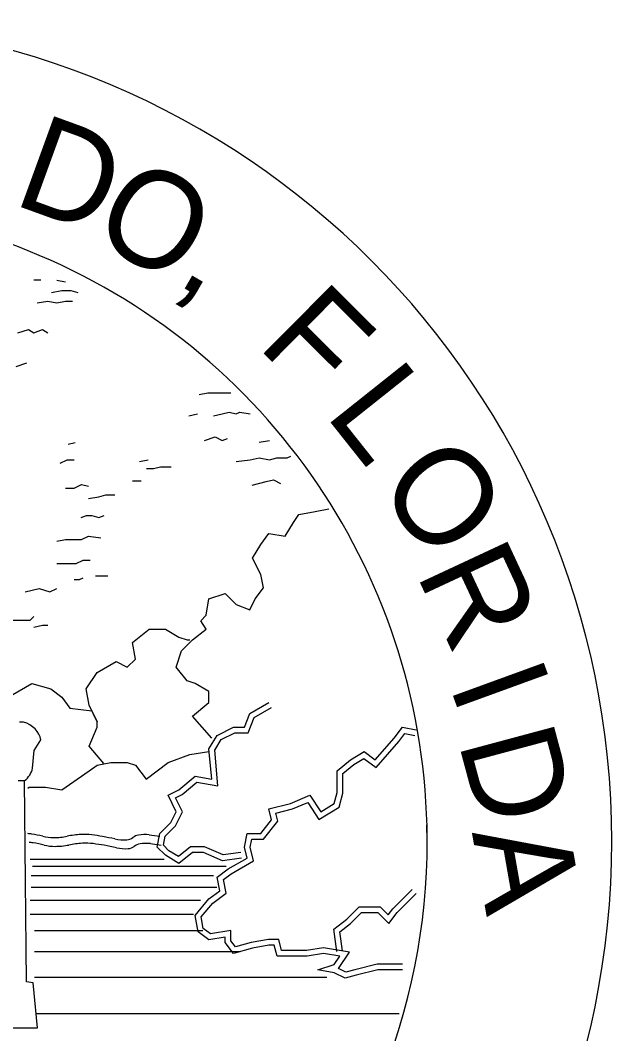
# Model space of a CAD drawing. Extents: x -7.1 to 10, y -5 to 6.
# Drawn here: x 6.3116 to 6.591, y -3.9297 to -3.4515 of the extents above; entities that cross this region are included whole.
import ezdxf

# ---------------------------------------------------------------- set-up
doc = ezdxf.new("R2010")
doc.units = 0
doc.layers.add('Level 60', color=7, linetype='Continuous')

msp = doc.modelspace()

# ---------------------------------------------------------------- linework, layer by layer
at = {"layer": 'Level 60'}
for p, q in [((6.321385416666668, -3.5740625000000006), (6.318031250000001, -3.5740625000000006)), ((6.328854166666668, -3.5740625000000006), (6.333010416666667, -3.574916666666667)), ((6.309708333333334, -3.614833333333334), (6.3146770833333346, -3.613135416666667)), ((6.391177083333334, -3.6380625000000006), (6.395343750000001, -3.6372395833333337)), ((6.334239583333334, -3.651583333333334), (6.337593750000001, -3.650739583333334)), ((6.4244062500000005, -3.6505208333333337), (6.429375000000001, -3.6497187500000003)), ((6.367895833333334, -3.6596666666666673), (6.372010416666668, -3.6588229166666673)), ((6.364593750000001, -3.6688125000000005), (6.368750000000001, -3.6688125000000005)), ((6.313083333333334, -3.782666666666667), (6.311218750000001, -3.782666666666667)), ((6.318218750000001, -3.7960937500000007), (6.321312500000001, -3.791083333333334)), ((6.318218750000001, -3.7960937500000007), (6.321312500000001, -3.791083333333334)), ((6.317416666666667, -3.8043645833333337), (6.318218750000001, -3.7960937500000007)), ((6.317416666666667, -3.8043645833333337), (6.318218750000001, -3.7960937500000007)), ((6.310656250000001, -3.8102500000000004), (6.313656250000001, -3.8102500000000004)), ((6.314645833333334, -3.905145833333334), (6.313656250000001, -3.8102500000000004)), ((6.372437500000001, -3.8358437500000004), (6.377593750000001, -3.836489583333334)), ((6.373145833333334, -3.8400104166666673), (6.37825, -3.8406666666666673)), ((6.316281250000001, -3.8473541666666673), (6.379666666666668, -3.8473541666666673)), ((6.317343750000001, -3.8506250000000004), (6.408906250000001, -3.8506250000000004)), ((6.316802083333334, -3.8550625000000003), (6.402854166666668, -3.8550625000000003)), ((6.316802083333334, -3.8605937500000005), (6.404489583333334, -3.8605937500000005)), ((6.316281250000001, -3.866645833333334), (6.396760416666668, -3.866645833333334)), ((6.316281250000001, -3.873239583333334), (6.393447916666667, -3.873239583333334)), ((6.318427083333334, -3.8810104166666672), (6.397895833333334, -3.8810104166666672)), ((6.318427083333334, -3.890916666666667), (6.415500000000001, -3.890916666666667)), ((6.317718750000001, -3.9056666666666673), (6.314645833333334, -3.905145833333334)), ((6.319708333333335, -3.9268437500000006), (6.317718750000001, -3.9056666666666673)), ((6.318427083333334, -3.9030625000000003), (6.456343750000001, -3.9030625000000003)), ((6.319020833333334, -3.920177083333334), (6.490520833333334, -3.920177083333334)), ((6.305104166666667, -3.9268437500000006), (6.319708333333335, -3.9268437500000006))]:
    msp.add_line(p, q, dxfattribs=at)
for points in [[(6.32634375, -3.579895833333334), (6.331333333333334, -3.579052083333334), (6.335447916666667, -3.579052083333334), (6.338822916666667, -3.579895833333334)], [(6.319687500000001, -3.5848854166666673), (6.3246979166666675, -3.5840625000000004), (6.328854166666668, -3.5848854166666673), (6.333010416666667, -3.5840625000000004), (6.336302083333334, -3.5840625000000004)], [(6.310531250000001, -3.599041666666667), (6.315520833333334, -3.5973437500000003), (6.318031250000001, -3.599041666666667), (6.322166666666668, -3.5973437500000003), (6.3246979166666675, -3.599041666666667)], [(6.396166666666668, -3.6281145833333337), (6.400281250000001, -3.6272916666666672), (6.404489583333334, -3.6272916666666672), (6.406968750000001, -3.6272916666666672), (6.411104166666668, -3.6272916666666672)], [(6.402854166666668, -3.6380625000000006), (6.406968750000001, -3.6372395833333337), (6.410302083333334, -3.636385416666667), (6.4136145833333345, -3.6372395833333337), (6.415260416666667, -3.636385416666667), (6.420270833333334, -3.6372395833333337)], [(6.398677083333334, -3.6497187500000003), (6.403656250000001, -3.6480416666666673), (6.406968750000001, -3.6497187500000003), (6.409447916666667, -3.648895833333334)], [(6.4136145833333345, -3.6596666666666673), (6.420270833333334, -3.6588229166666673), (6.4244062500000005, -3.658010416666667), (6.429375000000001, -3.6588229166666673), (6.432729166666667, -3.658010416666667), (6.437697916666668, -3.658010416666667), (6.439395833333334, -3.6572083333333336)], [(6.3304791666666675, -3.660520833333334), (6.3338125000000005, -3.6588229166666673), (6.337145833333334, -3.6588229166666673)], [(6.371229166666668, -3.663020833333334), (6.374520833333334, -3.663020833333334), (6.377875, -3.662197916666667), (6.382833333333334, -3.662197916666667)], [(6.333010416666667, -3.672197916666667), (6.337145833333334, -3.672197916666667), (6.340479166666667, -3.670489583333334), (6.343791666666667, -3.6713437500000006)], [(6.42121875, -3.6708750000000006), (6.427833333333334, -3.6691666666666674), (6.431166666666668, -3.6683645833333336), (6.434479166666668, -3.6700000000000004)], [(6.343791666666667, -3.6771562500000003), (6.348802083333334, -3.6763125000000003), (6.352083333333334, -3.6754791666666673), (6.356270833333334, -3.6754791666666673)], [(6.402031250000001, -3.7901875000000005), (6.393020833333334, -3.779854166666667), (6.400729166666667, -3.7734687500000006), (6.400729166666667, -3.7682708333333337), (6.394302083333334, -3.764447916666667), (6.390468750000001, -3.7631458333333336), (6.385291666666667, -3.7567395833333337), (6.387843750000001, -3.748989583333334), (6.393020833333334, -3.743833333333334), (6.399427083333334, -3.7387291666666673), (6.3968750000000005, -3.734833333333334), (6.399427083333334, -3.7322500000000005), (6.400729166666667, -3.7245520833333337), (6.408458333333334, -3.7220000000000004), (6.4136145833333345, -3.7271041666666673), (6.420041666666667, -3.7296562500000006), (6.422635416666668, -3.7245520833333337), (6.426489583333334, -3.7193750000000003), (6.425187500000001, -3.7129479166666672), (6.421364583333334, -3.705239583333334), (6.425187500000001, -3.6987812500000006), (6.429093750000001, -3.6936562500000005), (6.436770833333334, -3.6949375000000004), (6.440604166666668, -3.6885000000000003), (6.4431979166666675, -3.6846250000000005), (6.450927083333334, -3.683354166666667), (6.457385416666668, -3.6820729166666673)], [(6.340385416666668, -3.6860937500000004), (6.342895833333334, -3.685239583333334), (6.345395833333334, -3.685239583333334), (6.3487083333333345, -3.6860937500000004), (6.351239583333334, -3.685239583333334)], [(6.328854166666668, -3.6973229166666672), (6.333010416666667, -3.696520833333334), (6.337145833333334, -3.696520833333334), (6.340479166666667, -3.696520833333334), (6.343791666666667, -3.694885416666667), (6.3496250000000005, -3.6956875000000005)], [(6.328854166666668, -3.707864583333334), (6.3338125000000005, -3.707864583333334), (6.337979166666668, -3.707864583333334), (6.341312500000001, -3.706229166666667), (6.344645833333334, -3.706229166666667)], [(6.337145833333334, -3.715354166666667), (6.339635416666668, -3.715354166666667), (6.341312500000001, -3.714552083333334)], [(6.347125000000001, -3.7136979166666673), (6.350406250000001, -3.7136979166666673), (6.352916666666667, -3.7136979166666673)], [(6.313895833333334, -3.7211875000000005), (6.317197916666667, -3.7203645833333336), (6.320531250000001, -3.7195625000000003), (6.323010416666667, -3.7203645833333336), (6.325520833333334, -3.7211875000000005), (6.328854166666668, -3.7195625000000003)], [(6.303895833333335, -3.735354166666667), (6.307250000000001, -3.7345208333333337), (6.309708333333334, -3.7345208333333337), (6.313041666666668, -3.7345208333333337), (6.316354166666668, -3.7345208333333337), (6.318031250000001, -3.732822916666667)], [(6.318031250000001, -3.7378125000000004), (6.322166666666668, -3.736958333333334), (6.3246979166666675, -3.736958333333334)], [(6.351072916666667, -3.8021875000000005), (6.344125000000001, -3.794041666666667), (6.347979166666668, -3.785010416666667), (6.347979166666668, -3.782458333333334), (6.344125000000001, -3.7747291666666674), (6.342822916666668, -3.767020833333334), (6.347979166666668, -3.7593125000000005), (6.356979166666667, -3.754114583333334), (6.362135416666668, -3.7567395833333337), (6.365989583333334, -3.752885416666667), (6.3647083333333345, -3.7451354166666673), (6.372437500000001, -3.7387291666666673), (6.3801458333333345, -3.7387291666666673), (6.386572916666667, -3.7425625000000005), (6.390468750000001, -3.743833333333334), (6.391750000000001, -3.743833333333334)], [(6.263052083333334, -3.8197500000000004), (6.256604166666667, -3.815927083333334), (6.261750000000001, -3.8081979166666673), (6.268208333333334, -3.802989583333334), (6.273333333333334, -3.7953125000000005), (6.279760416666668, -3.7927604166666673), (6.288770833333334, -3.7862812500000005), (6.293947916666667, -3.7773020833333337), (6.299125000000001, -3.7734687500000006), (6.308052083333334, -3.769572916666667), (6.3170625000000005, -3.764447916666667), (6.326062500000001, -3.767020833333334), (6.331239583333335, -3.770895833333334), (6.33509375, -3.7760312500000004), (6.345395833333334, -3.7773020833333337), (6.347979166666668, -3.782458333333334)], [(6.416187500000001, -3.8468125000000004), (6.407177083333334, -3.8480937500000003), (6.3981770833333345, -3.844239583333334), (6.393020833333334, -3.844239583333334), (6.386572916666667, -3.8493645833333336), (6.3801458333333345, -3.8455104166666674), (6.376291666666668, -3.8416875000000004), (6.377593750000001, -3.835208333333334), (6.38271875, -3.830104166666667), (6.385291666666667, -3.8249270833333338), (6.3814375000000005, -3.8171770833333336), (6.386572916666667, -3.8146250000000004), (6.394302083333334, -3.8081979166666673), (6.402031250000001, -3.809520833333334), (6.400729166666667, -3.7953125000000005), (6.404625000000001, -3.7889270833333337), (6.4123333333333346, -3.785010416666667), (6.417458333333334, -3.785010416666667), (6.420041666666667, -3.778552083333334), (6.429093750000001, -3.7734687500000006)], [(6.415833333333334, -3.8441250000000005), (6.407531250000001, -3.845354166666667), (6.3987187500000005, -3.8415625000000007), (6.392072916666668, -3.8415625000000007), (6.386385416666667, -3.8461250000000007), (6.381791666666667, -3.843385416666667), (6.379239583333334, -3.8407604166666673), (6.380020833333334, -3.836489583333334), (6.384937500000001, -3.831666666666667), (6.388270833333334, -3.8249270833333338), (6.385010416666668, -3.8184062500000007), (6.388031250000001, -3.816864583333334), (6.395083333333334, -3.8110520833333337), (6.404979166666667, -3.8126875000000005), (6.403489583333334, -3.795927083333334), (6.406520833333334, -3.7909166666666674), (6.412947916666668, -3.787677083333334), (6.419302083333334, -3.787677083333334), (6.4221666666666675, -3.780447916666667), (6.4303645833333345, -3.7757187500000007)], [(6.492125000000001, -3.899572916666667), (6.480541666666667, -3.899572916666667), (6.470291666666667, -3.9021250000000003), (6.465083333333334, -3.9034479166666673), (6.4599375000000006, -3.9008958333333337), (6.452187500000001, -3.899572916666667), (6.4599375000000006, -3.897020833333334), (6.462510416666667, -3.893135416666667), (6.454781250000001, -3.891885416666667), (6.4471041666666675, -3.893135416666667), (6.440604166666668, -3.893135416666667), (6.432947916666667, -3.893135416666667), (6.431572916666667, -3.8879687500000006), (6.429093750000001, -3.8879687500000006), (6.421364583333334, -3.889260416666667), (6.4123333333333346, -3.891885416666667), (6.408458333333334, -3.886708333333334), (6.408458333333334, -3.884135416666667), (6.400729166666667, -3.8854062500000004), (6.395604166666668, -3.8815625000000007), (6.394302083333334, -3.8738750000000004), (6.400729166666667, -3.8661250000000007), (6.405906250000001, -3.862270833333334), (6.404625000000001, -3.855791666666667), (6.409760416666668, -3.8519687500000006), (6.4188125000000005, -3.8468125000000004), (6.417458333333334, -3.8416875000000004), (6.4188125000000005, -3.835208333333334), (6.425187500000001, -3.835208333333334), (6.4303437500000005, -3.8287812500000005), (6.429093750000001, -3.8236562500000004), (6.439322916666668, -3.8211250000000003), (6.448354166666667, -3.8171770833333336), (6.453510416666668, -3.8249270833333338), (6.4599375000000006, -3.8211250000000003), (6.461260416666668, -3.815927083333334), (6.461260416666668, -3.8055937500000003), (6.467666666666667, -3.800489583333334), (6.474114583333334, -3.7965937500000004), (6.47925, -3.800489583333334), (6.488250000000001, -3.7901875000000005), (6.492125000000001, -3.785010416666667), (6.498552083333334, -3.7862812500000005)], [(6.492125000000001, -3.8968958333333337), (6.480218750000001, -3.8968958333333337), (6.4696041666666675, -3.899572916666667), (6.465416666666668, -3.900604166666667), (6.461947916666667, -3.8988645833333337), (6.467072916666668, -3.891197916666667), (6.454781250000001, -3.889166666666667), (6.446843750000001, -3.890447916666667), (6.440604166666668, -3.890447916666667), (6.4350000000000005, -3.890447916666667), (6.4336979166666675, -3.8852916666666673), (6.428833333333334, -3.8852916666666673), (6.420750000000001, -3.886666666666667), (6.413354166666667, -3.888770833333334), (6.411156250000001, -3.885791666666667), (6.411156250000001, -3.8809479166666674), (6.401437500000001, -3.8825937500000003), (6.398062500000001, -3.880041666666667), (6.397135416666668, -3.874614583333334), (6.402593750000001, -3.8680833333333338), (6.408833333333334, -3.8634062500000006), (6.407562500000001, -3.8569062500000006), (6.411218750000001, -3.8541875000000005), (6.421854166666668, -3.8480937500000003), (6.420250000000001, -3.8415937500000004), (6.420958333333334, -3.8378541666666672), (6.426468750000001, -3.8378541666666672), (6.433229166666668, -3.8294166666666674), (6.432333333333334, -3.8255625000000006), (6.4402187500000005, -3.8236562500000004), (6.447385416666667, -3.820583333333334), (6.452697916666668, -3.8285729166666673), (6.462270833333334, -3.822822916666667), (6.463927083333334, -3.816229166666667), (6.463927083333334, -3.806916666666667), (6.469197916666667, -3.802708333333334), (6.473927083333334, -3.799854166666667), (6.479645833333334, -3.8041041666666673), (6.490375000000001, -3.7918437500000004), (6.493260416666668, -3.7879895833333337), (6.498010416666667, -3.788958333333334)], [(6.3151875, -3.8137916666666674), (6.315781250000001, -3.8133437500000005), (6.323531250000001, -3.8133437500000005), (6.331239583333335, -3.8146250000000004), (6.344125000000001, -3.8055937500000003), (6.347979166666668, -3.802989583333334), (6.354375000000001, -3.801760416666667), (6.362135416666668, -3.801760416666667), (6.365989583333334, -3.802989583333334), (6.371156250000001, -3.809520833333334), (6.3814375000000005, -3.801760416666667), (6.391750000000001, -3.7978854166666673), (6.400729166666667, -3.7965937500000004)], [(6.461135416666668, -3.8909375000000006), (6.459656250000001, -3.8803333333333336), (6.465916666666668, -3.875645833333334), (6.471708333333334, -3.8698333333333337), (6.481677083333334, -3.8698333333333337), (6.4854166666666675, -3.873614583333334), (6.487520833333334, -3.870802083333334), (6.496666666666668, -3.8616562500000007)], [(6.4638125, -3.890541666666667), (6.462510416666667, -3.8815625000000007), (6.467666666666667, -3.877708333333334), (6.472843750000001, -3.8725729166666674), (6.480541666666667, -3.8725729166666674), (6.485677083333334, -3.877708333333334), (6.489572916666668, -3.8725729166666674), (6.498552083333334, -3.863552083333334)]]:
    msp.add_lwpolyline(points, dxfattribs=at)
for centre, radius, start, end in [((6.203581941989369, -3.83889133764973), 0.38740662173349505, 0, 180), ((6.203581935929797, -3.8388913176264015), 0.3002401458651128, 359.2051583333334, 270.6060000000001), ((6.308060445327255, -3.802550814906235), 0.009529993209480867, 306.0672694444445, 348.8327222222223), ((6.308060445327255, -3.802550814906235), 0.009529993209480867, 306.0672694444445, 348.8327222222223), ((6.20358191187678, -3.838891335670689), 0.30024012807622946, 270.6060055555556, 1.4933611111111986), ((6.313221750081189, -3.862174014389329), 0.02695907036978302, 81.85670277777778, 85.95562222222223), ((6.203581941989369, -3.83889133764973), 0.38740662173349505, 180, 0), ((6.3139115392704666, -3.866315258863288), 0.02695907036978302, 81.85670277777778, 85.95562222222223), ((6.309755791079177, -3.8863980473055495), 0.05142980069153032, 75.96379722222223, 81.85704444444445), ((6.310445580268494, -3.8905392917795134), 0.05142980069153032, 75.96379722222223, 81.85704444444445), ((6.32740001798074, -3.8158209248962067), 0.021319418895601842, 255.96379722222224, 270.0000416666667), ((6.3274000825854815, -3.80450402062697), 0.032636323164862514, 269.9999138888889, 281.33466111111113), ((6.342760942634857, -3.881135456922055), 0.04551950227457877, 93.14822222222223, 101.33487500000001), ((6.343450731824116, -3.885276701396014), 0.04551950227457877, 93.14822222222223, 101.33487500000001), ((6.3418258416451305, -3.864137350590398), 0.02849569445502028, 82.79555277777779, 93.14788611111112), ((6.342515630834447, -3.868278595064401), 0.02849569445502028, 82.79555277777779, 93.14788611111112), ((6.332294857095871, -3.939540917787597), 0.10449923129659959, 79.94893333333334, 82.79590555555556), ((6.332984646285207, -3.943682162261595), 0.10449923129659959, 79.94893333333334, 82.79590555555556), ((6.326743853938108, -3.9708553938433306), 0.13630190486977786, 77.45590833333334, 79.94867222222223), ((6.3604724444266, -3.8192675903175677), 0.018992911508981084, 257.4559888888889, 274.451725), ((6.36153601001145, -3.8329292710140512), 0.005289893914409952, 274.4522777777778, 306.97325555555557), ((6.368541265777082, -3.8422346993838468), 0.006357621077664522, 99.47968888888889, 126.97268333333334), ((6.3702964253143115, -3.8527462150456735), 0.017014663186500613, 82.7755138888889, 99.47957500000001), ((6.370986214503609, -3.8568874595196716), 0.017014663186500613, 82.7755138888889, 99.47957500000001), ((6.328089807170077, -3.8199621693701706), 0.021319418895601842, 255.96379722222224, 270.0000416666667), ((6.328089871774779, -3.8086452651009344), 0.032636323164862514, 269.9999138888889, 281.33466111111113), ((6.327433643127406, -3.9749966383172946), 0.13630190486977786, 77.45590833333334, 79.94867222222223), ((6.361162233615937, -3.8234088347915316), 0.018992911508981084, 257.4559888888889, 274.451725), ((6.362225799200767, -3.8370705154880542), 0.005289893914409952, 274.4522777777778, 306.97325555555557), ((6.369231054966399, -3.8463759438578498), 0.006357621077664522, 99.47968888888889, 126.97268333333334)]:
    msp.add_arc(centre, radius, start, end, dxfattribs=at)
msp.add_ellipse((6.3092060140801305, -3.79274413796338), major_axis=(0.012298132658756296, -3.0121737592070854e-18), ratio=0.864878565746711, start_param=0.15694063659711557, end_param=1.2486851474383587, dxfattribs=at)
msp.add_ellipse((6.3092060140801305, -3.79274413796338), major_axis=(0.012298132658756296, -3.0121737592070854e-18), ratio=0.864878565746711, start_param=0.15694063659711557, end_param=1.2486851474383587, dxfattribs=at)

# ---------------------------------------------------------------- texts
for s, height, rotation, p in [('D', 0.04564018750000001, 340, (6.307302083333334, -3.537947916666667)), ('O', 0.04564018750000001, 330.00000000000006, (6.343604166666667, -3.5534062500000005)), (',', 0.04564018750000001, 330.00000000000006, (6.384375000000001, -3.575239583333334)), ('F', 0.04564018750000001, 315.18892222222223, (6.422968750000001, -3.6051875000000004)), ('L', 0.04564012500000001, 308.4768777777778, (6.455062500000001, -3.6373541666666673)), ('O', 0.04564018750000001, 310.0000027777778, (6.478864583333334, -3.6727187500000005)), ('R', 0.04564018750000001, 295, (6.4982708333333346, -3.7122812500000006)), ('I', 0.04564018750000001, 290, (6.5140625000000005, -3.7649687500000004)), ('D', 0.04564018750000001, 285.00000000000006, (6.518385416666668, -3.7918437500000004)), ('A', 0.04564018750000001, 280.00000000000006, (6.524906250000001, -3.834739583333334))]:
    msp.add_text(s, height=height, rotation=rotation, dxfattribs=at).set_placement(p)

doc.saveas('drawing.dxf')
